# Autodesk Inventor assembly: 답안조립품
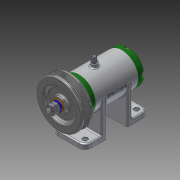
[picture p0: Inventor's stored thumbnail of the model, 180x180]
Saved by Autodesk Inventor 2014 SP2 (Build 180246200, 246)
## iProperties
Created: 2017-02
Part Number: 답안조립품
Document SubType Name: Assembly
Designer: 거성
Author: 거성
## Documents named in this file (16)
- C:\Users\거성\Desktop\470208V1021\답안조립품.iam
- C:\Users\거성\Desktop\470208V1021\본체.ipt
- C:\Users\거성\Desktop\470208V1021\베어링 15 x 32 x 9.ipt
- C:\Users\거성\Desktop\470208V1021\앞커버.ipt
- C:\Users\거성\Desktop\470208V1021\뒤커버.ipt
- C:\Users\거성\Desktop\470208V1021\오일 실 15 25 7.ipt
- C:\Users\거성\Desktop\470208V1021\볼트 M4 x 12.ipt
- C:\Users\거성\Desktop\470208V1021\축.ipt
- C:\Users\거성\Desktop\470208V1021\키 3 x 3 x 12.ipt
- C:\Users\거성\Desktop\470208V1021\V벨트풀리.ipt
- C:\Users\거성\Desktop\470208V1021\와셔 8x17.ipt
- C:\Users\거성\Desktop\470208V1021\스프링와셔 8.ipt
- C:\Users\거성\Desktop\470208V1021\너트 M 8.ipt
- C:\Users\거성\Desktop\470208V1021\와셔 6x11.5.ipt
- C:\Users\거성\Desktop\470208V1021\볼트 M 6 x 8.ipt
- C:\Users\거성\Desktop\470208V1021\니플 M 6 x 0.75.ipt
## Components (11 placed, 3 different names)
1. KS B 2023 6002 - 15 x 32 x 9:1
2. KS B 2023 6002 - 15 x 32 x 9:2
3. V벨트풀리:1 — 각도:2
4. ISO 4762 M4 x 12:1
5. ISO 4762 M4 x 12:3
6. ISO 4762 M4 x 12:4
7. ISO 4762 M4 x 12:5
8. ISO 4762 M4 x 12:2
9. ISO 4762 M4 x 12:6
10. ISO 4762 M4 x 12:7
11. ISO 4762 M4 x 12:8
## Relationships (1: Angle 1)
- 각도:2 [Angle]: V벨트풀리:1
